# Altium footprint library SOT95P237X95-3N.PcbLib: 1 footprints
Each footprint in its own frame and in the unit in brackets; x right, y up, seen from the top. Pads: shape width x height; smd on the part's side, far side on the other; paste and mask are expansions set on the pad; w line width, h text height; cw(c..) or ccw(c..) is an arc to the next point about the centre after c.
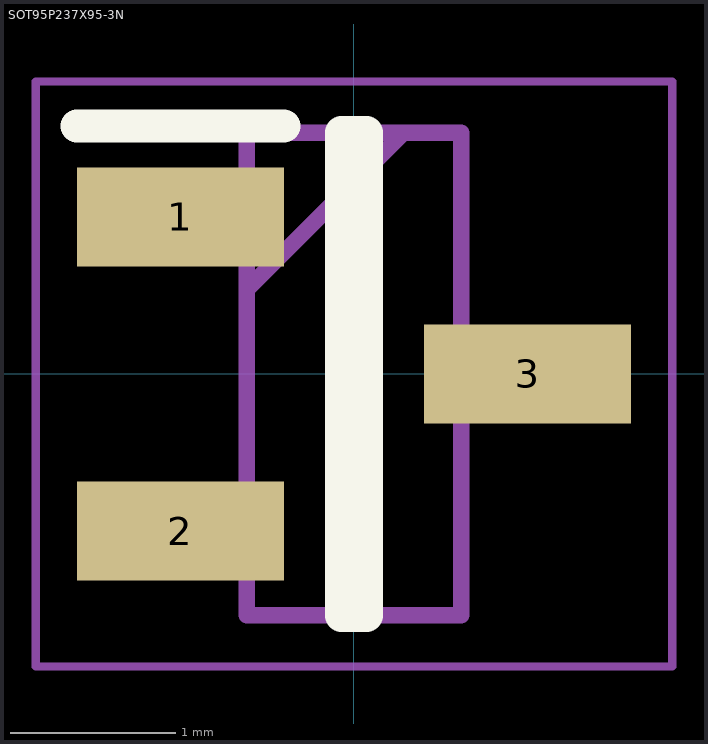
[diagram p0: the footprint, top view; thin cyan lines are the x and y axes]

## SOT95P237X95-3N [mm]
pads (3):
  rect 1.25x0.6 smd: 1(-1.05,0.95) 2(-1.05,-0.95) 3(1.05,0)
Top Overlay:
  lines w0.2: -1.675,1.5 -0.425,1.5 ; -0.075,-1.46 0.075,-1.46 0.075,1.46 -0.075,1.46 -0.075,-1.46
Mechanical 15:
  lines w0.1: -0.65,0.51 0.3,1.46 ; -0.65,-1.46 0.65,-1.46 0.65,1.46 -0.65,1.46 -0.65,-1.46
Mechanical 20:
  lines w0.05: -1.925,-1.77 1.925,-1.77 1.925,1.77 -1.925,1.77 -1.925,-1.77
